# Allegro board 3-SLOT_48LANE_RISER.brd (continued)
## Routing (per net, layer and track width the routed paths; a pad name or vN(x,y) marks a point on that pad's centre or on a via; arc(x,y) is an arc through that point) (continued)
PE_SLV_RX_DN<15>: length 8.6
  TOP w0.135: C102.2 13.17,79.65 13.02,79.65 9.99,79.18 9.4,79.18 v2(9.17,79.41)
  BOTTOM w0.135: J8.24 12.29,79.33 12.14,79.18 9.4,79.18 v2(9.17,79.41)
PE_SLV_RX_DP<0>: length 6
  TOP w0.135: v2(10.82,38.79) 11.03,38.99 13.98,38.99 C23.2
  BOTTOM w0.135: J7.2 12.31,38.87 12.16,39.02 11.06,39.02 v2(10.82,38.79)
PE_SLV_RX_DP<1>: length 9.2
  TOP w0.135: C24.2 13.99,41.01 12.52,41.01 10.32,40.82 v6(10.18,40.82) 9.43,40.82 v2(9.2,40.59)
  BOTTOM w0.135: v2(9.2,40.59) 9.43,40.82 12.17,40.82 12.31,40.68 J7.5
PE_SLV_RX_DP<2>: length 6
  TOP w0.135: C25.2 13.93,43.11 13.35,43.11 v6(12.89,42.95) 11.97,42.63 11.08,42.63 v2(10.85,42.4)
  BOTTOM w0.135: J7.8 12.32,42.48 12.17,42.62 11.07,42.62 v2(10.85,42.4)
PE_SLV_RX_DP<3>: length 9.3
  TOP w0.135: v2(9.22,44.2) 9.45,44.43 11.29,44.43 v6(12.91,44.99) 13.35,45.14 13.93,45.14 C26.2
  BOTTOM w0.135: v2(9.22,44.2) 9.44,44.42 12.17,44.42 12.32,44.27 J7.11
PE_SLV_RX_DP<4>: length 6.1
  TOP w0.135: C79.2 13.93,47.17 13.46,47.17 v6(13.17,47.02) 11.9,46.34 11.9,46.33 11.61,46.18 11.1,46.18 v2(10.9,45.98)
  BOTTOM w0.135: J7.14 12.32,46.08 12.18,46.22 11.14,46.22 v2(10.9,45.98)
PE_SLV_RX_DP<5>: length 9.6
  TOP w0.135: v2(9.2,47.81) 9.42,48.03 v6(10.07,48.03) 11.28,48.03 12.19,48.36 13.25,49.16 13.62,49.23 13.91,49.23 C80.2
  BOTTOM w0.135: J7.17 12.3,47.87 12.16,48.02 9.41,48.02 v2(9.2,47.81)
PE_SLV_RX_DP<6>: length 6.2
  TOP w0.135: C81.2 13.98,51.18 13.36,51.18 13.18,51.1 12.1,50.12 11.9,50 11.56,49.81 11.15,49.81 v2(10.92,49.58)
  BOTTOM w0.135: v2(10.92,49.58) 11.16,49.82 12.18,49.82 12.33,49.68 J7.20
PE_SLV_RX_DP<7>: length 9.8
  TOP w0.135: v2(9.2,51.41) 9.43,51.64 11.22,51.64 12.13,52.02 13.05,52.93 13.55,53.25 13.94,53.25 C82.2
  BOTTOM w0.135: v2(9.2,51.41) 9.41,51.62 12.19,51.62 12.34,51.48 J7.23
PE_SLV_RX_DP<8>: length 5.4
  TOP w0.135: C83.2 13.17,65.12 12.85,65.12 11.78,66.12 11.32,66.27 11.15,66.27 v2(10.92,66.04)
  BOTTOM w0.135: J8.2 12.25,66.13 12.1,66.27 11.15,66.27 v2(10.92,66.04)
PE_SLV_RX_DP<9>: length 8.6
  TOP w0.135: v2(9.22,67.85) 9.45,68.08 10.4,68.08 v6(11.02,67.95) 11.92,67.76 12.71,67.21 12.79,67.15 13.17,67.15 C84.2
  BOTTOM w0.135: J8.5 12.24,67.93 12.1,68.07 9.45,68.07 v2(9.22,67.85)
PE_SLV_RX_DP<10>: length 5.2
  TOP w0.135: v2(10.92,69.65) 11.15,69.88 11.4,69.88 12.9,69.18 13.17,69.18 C85.2
  BOTTOM w0.135: v2(10.92,69.65) 11.15,69.87 12.15,69.87 12.3,69.73 J8.8
PE_SLV_RX_DP<11>: length 8.5
  TOP w0.135: v2(9.2,71.46) 9.43,71.68 10.18,71.68 v6(10.66,71.6) 12.88,71.22 12.9,71.21 13.17,71.21 C86.2
  BOTTOM w0.135: v2(9.2,71.46) 9.41,71.67 12.18,71.67 12.33,71.53 J8.11
PE_SLV_RX_DP<12>: length 5
  TOP w0.135: C87.2 13.17,73.25 12.85,73.25 11.35,73.46 11.15,73.46 v2(10.92,73.23)
  BOTTOM w0.135: J8.14 12.3,73.33 12.16,73.47 11.16,73.47 v2(10.92,73.23)
PE_SLV_RX_DP<13>: length 8.5
  TOP w0.135: v2(9.17,75.06) 9.4,75.29 v6(10.14,75.29) 13.15,75.29 C88.2
  BOTTOM w0.135: v2(9.17,75.06) 9.38,75.27 12.16,75.27 12.31,75.13 J8.17
PE_SLV_RX_DP<14>: length 5
  TOP w0.135: v2(10.92,76.84) 11.15,77.07 11.39,77.07 12.94,77.31 13.17,77.31 C89.2
  BOTTOM w0.135: v2(10.92,76.84) 11.16,77.07 12.16,77.07 12.31,76.93 J8.20
PE_SLV_RX_DP<15>: length 8.6
  TOP w0.135: v2(9.17,78.64) 9.4,78.87 10.02,78.87 13.05,79.34 13.17,79.34 C90.2
  BOTTOM w0.135: v2(9.17,78.64) 9.4,78.87 12.14,78.87 12.29,78.73 J8.23
PE_SLV_TX_DN<0>: length 49
  BOTTOM w0.135: J7.48 16.49,39.48 16.63,39.33 18.14,39.33 20.01,39.92 21.23,40.77 21.27,40.99 21.78,41.35 22,41.31 22.36,41.56 22.4,41.78 22.91,42.13 23.12,42.1 25.06,43.46 25.1,43.65 25.58,43.99 25.77,43.95 26.13,44.21 26.17,44.4 26.65,44.74 26.84,44.7 27.64,45.26 33.05,52.99 v6(35.52,56.51) 37.51,59.36 44.62,64.33 48.97,65.1 52.01,65.64 52.7,66.33 52.7,66.52 U1.AE1
PE_SLV_TX_DN<1>: length 48.3
  BOTTOM w0.089: U1.AE2 52.28,67.39 51.32,67.39 51.25,67.38 51.19,67.42 51.16,67.42
  BOTTOM w0.135: J7.45 16.49,41.27 16.64,41.13 17.86,41.13 19.41,41.61 20.2,42.17 20.24,42.41 20.7,42.73 20.93,42.68 21.29,42.94 21.33,43.16 21.8,43.49 22.03,43.45 27.36,47.18 28.32,48.55 28.28,48.76 28.6,49.22 28.81,49.25 29.06,49.61 29.02,49.82 29.35,50.28 29.55,50.31 31.68,53.36 31.65,53.56 31.97,54.02 32.17,54.06 33.82,56.41 33.78,56.62 34.06,57.02 34.27,57.06 v6(35.42,58.69) 37.04,61.01 44.52,66.25 47.66,66.8 51.16,67.42
PE_SLV_TX_DN<2>: length 48.4
  BOTTOM w0.089: 49.52,68.35 49.55,68.35 49.6,68.29 50.24,68.29 50.55,68.35 51.35,68.89 51.92,68.99 52.28,68.99 U1.AE4
  BOTTOM w0.135: J7.42 16.52,43.08 16.67,42.93 17.97,42.93 19.06,43.12 19.79,43.63 19.83,43.84 20.23,44.12 20.44,44.09 20.8,44.34 20.83,44.54 21.23,44.83 21.44,44.79 26.39,48.25 27.28,49.53 27.25,49.72 27.59,50.2 27.77,50.23 28.02,50.59 27.99,50.78 28.33,51.26 28.51,51.29 30.64,54.32 30.61,54.49 30.88,54.89 31.05,54.92 31.31,55.28 31.28,55.45 31.55,55.84 31.72,55.87 33.93,59.02 33.89,59.24 34.21,59.69 34.42,59.73 36.14,62.17 v6(37.61,63.21) 43.95,67.65 46.72,68.14 47.63,68.3 47.63,68.3 47.93,68.35 49.52,68.35
PE_SLV_TX_DN<3>: length 47.9
  BOTTOM w0.089: U1.AE5 52.28,69.79 52.07,69.79 50.67,69.54 49.29,69.54 49.23,69.6 49.21,69.6
  BOTTOM w0.135: 49.21,69.6 47.01,69.6 43.25,68.94 v6(40.42,66.96) 34.78,63.01 30.57,56.99 30.37,56.96 30.02,56.47 30.06,56.27 29.81,55.91 29.61,55.87 29.26,55.38 29.3,55.18 27.29,52.32 27.08,52.28 26.79,51.86 26.83,51.65 26.58,51.29 26.37,51.25 26.07,50.84 26.11,50.63 25.32,49.5 21.26,46.65 21.06,46.69 20.7,46.44 20.66,46.24 20.3,45.98 20.1,46.02 19.74,45.77 19.71,45.57 18.92,45.02 17.28,44.73 16.71,44.73 16.56,44.87 J7.39
PE_SLV_TX_DN<4>: length 47.8
  BOTTOM w0.089: U1.AE7 52.3,71.41 51.95,71.41 51.52,71.33 51.04,71 50.88,70.89 50.31,70.79 50.05,70.79 49.96,70.89 49.57,70.89 49.47,70.79 49.05,70.79 49,70.85 48.97,70.85
  BOTTOM w0.135: J7.36 16.56,46.68 16.7,46.53 17.65,46.53 18.59,46.69 19.32,47.21 19.36,47.42 19.72,47.67 19.93,47.63 20.29,47.89 20.33,48.1 20.69,48.35 20.9,48.31 24.27,50.67 25.2,52 25.16,52.2 25.41,52.56 25.61,52.59 25.87,52.95 25.83,53.15 26.08,53.51 26.28,53.54 28.15,56.22 28.12,56.41 28.48,56.93 28.67,56.96 28.93,57.32 28.89,57.52 29.25,58.04 29.45,58.07 33.37,63.67 v6(36.92,66.16) 42.51,70.07 46.95,70.85 48.97,70.85
PE_SLV_TX_DN<5>: length 47.2
  BOTTOM w0.089: 49.24,72.05 49.27,72.05 49.32,72 50.09,72 51.18,72.19 52.28,72.19 U1.AE8
  BOTTOM w0.135: 49.24,72.05 46.81,72.05 41.93,71.19 v6(33.34,65.18) 31.61,63.97 29.68,61.21 29.48,61.17 29.21,60.78 29.24,60.58 28.08,58.93 27.88,58.9 27.56,58.43 27.6,58.23 27.35,57.87 27.15,57.84 26.82,57.38 26.86,57.18 25.21,54.83 25.01,54.79 24.73,54.4 24.77,54.2 24.52,53.83 24.32,53.8 24.04,53.4 24.07,53.2 23.42,52.26 20.38,50.14 20.2,50.17 19.78,49.88 19.75,49.7 19.39,49.45 19.21,49.48 18.8,49.19 18.76,49 18,48.47 17.2,48.33 16.79,48.33 16.64,48.48 J7.33
PE_SLV_TX_DN<6>: length 46.9
  BOTTOM w0.089: U1.AE10 52.3,73.81 51.66,73.81 51.3,73.75 50.54,73.23 50.35,73.2 49.05,73.2 49,73.25 48.97,73.25
  BOTTOM w0.135: J7.30 16.54,50.27 16.73,50.09 17.4,50.09 18.5,50.78 18.54,50.98 18.91,51.21 19.11,51.17 19.48,51.41 19.52,51.6 19.89,51.84 20.08,51.79 21.14,52.47 21.78,53.38 21.74,53.59 22.02,53.98 22.23,54.02 22.48,54.38 22.44,54.59 22.72,54.98 22.93,55.02 25.49,58.68 25.45,58.88 25.73,59.27 25.93,59.31 26.18,59.67 26.15,59.87 26.42,60.26 26.62,60.3 v6(27.92,62.14) 28.88,63.53 41.49,72.35 46.62,73.25 48.97,73.25
PE_SLV_TX_DN<7>: length 46.5
  BOTTOM w0.089: 48.97,74.46 49,74.46 49.05,74.4 50.18,74.4 50.37,74.59 52.28,74.59 U1.AE11
  BOTTOM w0.135: 48.97,74.46 46.3,74.46 40.92,73.51 38.62,71.89 38.42,71.93 38.06,71.68 38.03,71.48 37.67,71.23 37.48,71.27 37.12,71.01 37.08,70.82 35.17,69.48 34.97,69.51 34.54,69.21 34.5,69.02 34.14,68.76 33.95,68.8 33.52,68.5 33.48,68.3 30.44,66.17 v6(28.61,64.89) 27.1,63.83 25.3,61.27 25.1,61.23 24.85,60.87 24.89,60.67 24.63,60.31 24.43,60.27 24.18,59.91 24.21,59.71 21.8,56.26 21.6,56.22 21.35,55.86 21.38,55.66 20.2,53.98 17.25,51.91 16.66,51.91 16.5,52.08 J7.27
PE_SLV_TX_DN<8>: length 39.3
  BOTTOM w0.089: U1.AE13 52.31,76.22 49.05,76.22 49,76.27 48.97,76.27
  BOTTOM w0.135: J8.48 16.49,66.73 16.63,66.58 17.82,66.58 17.95,66.71 18.47,66.71 18.61,66.58 19.05,66.58 19.18,66.71 19.7,66.71 19.83,66.58 21.59,66.58 22.6,67.04 22.68,67.24 23.08,67.42 23.28,67.35 23.68,67.53 23.76,67.73 24.16,67.91 24.36,67.84 30.15,70.48 30.23,70.68 30.7,70.9 30.9,70.82 31.3,71 31.37,71.21 31.84,71.42 32.04,71.35 37.04,73.63 v6(38.52,74.3) 39.5,74.75 48.17,76.27 48.97,76.27
PE_SLV_TX_DN<9>: length 39.3
  BOTTOM w0.089: 48.97,77.48 49.03,77.42 49.87,77.42 50.3,76.99 52.28,76.99 U1.AE14
  BOTTOM w0.135: 48.97,77.48 48.06,77.48 47.66,77.4 39.08,75.89 v6(36.4,74.78) 31.34,72.69 31.15,72.77 30.74,72.6 30.66,72.41 30.26,72.24 30.07,72.32 29.66,72.15 29.58,71.96 23.85,69.58 23.65,69.67 23.21,69.48 23.13,69.28 22.72,69.12 22.52,69.2 22.08,69.02 22,68.82 20.94,68.38 19.97,68.38 19.82,68.53 19.28,68.53 19.13,68.38 18.69,68.38 18.54,68.53 18,68.53 17.85,68.38 16.64,68.38 16.49,68.53 J8.45
PE_SLV_TX_DN<10>: length 38.9
  BOTTOM w0.089: 48.97,78.7 49,78.7 49.05,78.64 49.4,78.64 49.49,78.74 49.94,78.74 50.04,78.64 52.33,78.64 U1.AE16
  BOTTOM w0.135: 48.97,78.7 47.95,78.7 v6(44.41,78.07) 42.97,77.82 36.45,76.67 29.77,73.9 29.57,73.98 29.13,73.8 29.05,73.61 23.91,71.48 23.7,71.57 23.26,71.39 23.17,71.17 22.77,71 22.56,71.09 22.11,70.91 22.03,70.7 20.77,70.18 19.71,70.18 19.56,70.33 19.12,70.33 18.97,70.18 18.53,70.18 18.37,70.33 17.93,70.33 17.78,70.18 16.67,70.18 16.52,70.33 J8.42
PE_SLV_TX_DN<11>: length 39
  BOTTOM w0.089: U1.AE17 52.28,79.39 51.26,79.39 51.2,79.45 51.14,79.5 50.75,79.5 50.69,79.45 50.64,79.39 50.33,79.39 49.88,79.84 49.05,79.84 49,79.9 48.97,79.9
  BOTTOM w0.135: J8.39 16.56,72.13 16.71,71.98 17.69,71.98 17.84,72.13 18.28,72.13 18.44,71.98 18.88,71.98 19.03,72.13 19.47,72.13 19.62,71.98 21.12,71.98 22.49,72.54 22.57,72.74 22.98,72.91 23.18,72.83 23.58,73 23.67,73.2 24.07,73.37 24.27,73.28 29.15,75.3 29.23,75.5 29.64,75.67 29.84,75.59 31.06,76.1 34.87,77.67 v6(40.63,78.69) 47.51,79.9 47.84,79.9 47.93,79.98 48.47,79.98 48.55,79.9 48.97,79.9
PE_SLV_TX_DN<12>: length 38.7
  BOTTOM w0.089: 48.97,81.1 49,81.1 49.05,81.05 49.81,81.05 49.94,80.91 50.56,80.91 50.7,81.05 51.09,81.05 51.23,80.91 52.2,80.91 U1.AE19
  BOTTOM w0.135: 48.97,81.1 47.4,81.1 v6(35.78,79.05) 33.17,78.59 29.71,77.16 29.53,77.24 29.05,77.04 28.98,76.86 25.07,75.24 24.87,75.32 24.42,75.13 24.34,74.94 23.93,74.77 23.74,74.85 23.28,74.66 23.2,74.46 21.54,73.78 19.78,73.78 19.7,73.85 19.63,73.93 19.19,73.93 19.11,73.85 19.04,73.78 18.6,73.78 18.53,73.85 18.45,73.93 18.01,73.93 17.94,73.85 17.86,73.78 16.7,73.78 16.56,73.93 J8.36
PE_SLV_TX_DN<13>: length 38.6
  BOTTOM w0.089: U1.AE20 52.28,81.79 51.67,81.79 51.21,82.25 50.65,82.25 50.6,82.3 50.55,82.35 50.15,82.35 50.1,82.3 50.05,82.25 49.03,82.25 48.97,82.3
  BOTTOM w0.135: J8.33 16.64,75.73 16.79,75.58 17.69,75.58 17.76,75.64 17.76,75.65 17.83,75.71 18.27,75.71 18.33,75.65 18.33,75.64 18.4,75.58 18.84,75.58 18.91,75.64 18.91,75.65 18.97,75.71 19.41,75.71 19.48,75.65 19.48,75.64 19.55,75.58 21.67,75.58 23.54,76.35 23.63,76.56 24.03,76.73 24.24,76.64 24.65,76.81 24.74,77.02 25.14,77.19 25.35,77.1 28.16,78.26 28.23,78.44 28.69,78.63 28.87,78.56 29.98,79.02 29.98,79.02 30.96,79.42 36.49,80.4 v6(37.78,80.63) 47.28,82.3 48.97,82.3
PE_SLV_TX_DN<14>: length 38.4
  BOTTOM w0.089: 48.97,83.51 49.03,83.45 52.34,83.45 U1.AE22
  BOTTOM w0.135: J8.30 16.54,77.53 16.73,77.34 17.84,77.34 17.92,77.42 18,77.5 18.44,77.5 18.52,77.42 18.6,77.34 19.04,77.34 19.12,77.42 19.2,77.5 19.64,77.5 19.72,77.42 19.8,77.34 22.29,77.34 23.57,77.87 23.65,78.06 24.05,78.22 24.24,78.15 24.65,78.31 24.73,78.5 25.13,78.67 25.32,78.59 29.76,80.43 31.02,80.66 31.13,80.82 31.64,80.91 31.8,80.79 v6(34.51,81.27) 45.11,83.14 45.2,83.27 45.76,83.37 45.89,83.28 47.17,83.51 47.81,83.51 47.92,83.62 48.41,83.62 48.52,83.51 48.97,83.51
PE_SLV_TX_DN<15>: length 38.4
  BOTTOM w0.089: 48.97,84.71 49,84.71 49.05,84.65 49.7,84.65 50.16,84.19 52.28,84.19 U1.AE23
  BOTTOM w0.135: 48.97,84.71 47.7,84.71 47.54,84.86 47.1,84.86 46.95,84.71 46.05,84.71 v6(32.93,82.39) 31.34,82.11 31.16,82.24 30.72,82.16 30.6,81.98 29.12,81.72 25.59,80.26 25.41,80.33 24.97,80.15 24.89,79.97 24.49,79.8 24.31,79.87 23.86,79.69 23.79,79.51 22.96,79.16 20.79,79.16 20.71,79.24 20.63,79.32 20.19,79.32 20.11,79.24 20.03,79.16 19.59,79.16 19.51,79.24 19.43,79.32 19,79.32 18.92,79.24 18.84,79.16 16.66,79.16 16.5,79.33 J8.27
PE_SLV_TX_DP<0>: length 49
  BOTTOM w0.135: J7.49 16.44,38.87 16.59,39.02 18.19,39.02 20.15,39.64 27.86,45.04 v6(33.3,52.81) 35.77,56.33 36.54,57.44 37.73,59.14 44.74,64.05 48.97,64.79 52.16,65.35 53.01,66.2 53.01,66.52 U1.AD1
PE_SLV_TX_DP<1>: length 48.4
  BOTTOM w0.089: U1.AD2 53.04,67.57 52.67,67.2 51.34,67.2 51.28,67.18 51.24,67.12 51.22,67.12
  BOTTOM w0.135: J7.46 16.47,40.68 16.61,40.82 17.91,40.82 19.54,41.34 23.41,44.05 27.58,46.96 34.24,56.48 35.67,58.51 35.67,58.51 36.71,60.01 v6(36.82,60.16) 37.26,60.79 44.64,65.96 47.66,66.49 51.22,67.12
PE_SLV_TX_DP<2>: length 48.4
  BOTTOM w0.089: U1.AD4 52.73,68.8 51.93,68.8 51.42,68.71 50.63,68.17 50.32,68.1 49.6,68.1 49.55,68.05 49.52,68.05
  BOTTOM w0.135: 49.52,68.05 48.05,68.05 47.68,68 44.07,67.36 v6(38.82,63.68) 37.79,62.96 36.35,61.96 26.6,48.03 19.18,42.83 17.98,42.62 17.96,42.62 16.64,42.62 16.49,42.48 J7.43
PE_SLV_TX_DP<3>: length 48
  BOTTOM w0.089: U1.AD5 52.73,69.6 52.08,69.6 50.69,69.35 49.29,69.35 49.23,69.3 49.21,69.3
  BOTTOM w0.135: J7.40 16.57,44.27 16.72,44.42 17.31,44.42 19.04,44.73 25.54,49.28 35,62.79 40.59,66.71 v6(41.83,67.57) 43.37,68.65 47.03,69.3 49.21,69.3
PE_SLV_TX_DP<4>: length 47.9
  BOTTOM w0.089: 48.97,70.55 49,70.55 49.05,70.6 50.39,70.6 50.95,70.71 51.14,70.84 51.59,71.15 51.97,71.22 52.69,71.22 53.04,71.57 U1.AD7
  BOTTOM w0.135: J7.37 16.55,46.08 16.7,46.22 17.68,46.22 18.7,46.4 24.49,50.45 33.59,63.45 37.1,65.91 v6(38.32,66.77) 42.63,69.78 46.98,70.55 48.97,70.55
PE_SLV_TX_DP<5>: length 47.2
  BOTTOM w0.089: U1.AD8 52.73,72 51.19,72 50.1,71.81 49.32,71.81 49.27,71.75 49.24,71.75
  BOTTOM w0.135: J7.34 16.62,47.87 16.77,48.02 17.23,48.02 18.11,48.18 23.64,52.04 31.83,63.75 33.51,64.93 v6(34.89,65.89) 42.05,70.9 46.84,71.75 49.24,71.75
PE_SLV_TX_DP<6>: length 47
  BOTTOM w0.089: U1.AD10 52.76,73.62 52.13,73.62 52.12,73.62 51.68,73.62 51.37,73.57 50.61,73.05 50.43,73.01 49.05,73.01 49,72.95 48.97,72.95
  BOTTOM w0.135: 48.97,72.95 46.64,72.95 41.61,72.06 v6(30.47,64.27) 29.1,63.31 28.17,61.97 27.81,61.46 27.81,61.45 21.36,52.24 17.49,49.78 16.65,49.78 16.55,49.68 J7.31
PE_SLV_TX_DP<7>: length 46.6
  BOTTOM w0.089: U1.AD11 53.04,74.76 52.67,74.4 50.44,74.4 50.26,74.21 49.05,74.21 49,74.15 48.97,74.15
  BOTTOM w0.135: 48.97,74.15 46.33,74.15 41.04,73.22 v6(30.61,65.92) 28.79,64.64 27.32,63.61 20.42,53.76 17.35,51.61 16.59,51.61 16.45,51.48 J7.28
PE_SLV_TX_DP<8>: length 39.4
  BOTTOM w0.089: U1.AD13 52.6,76.01 52.5,76.02 52.17,76.02 52.16,76.03 49.05,76.03 49,75.97 48.97,75.97
  BOTTOM w0.135: J8.49 16.44,66.13 16.59,66.27 21.66,66.27 v6(37.17,73.35) 38.65,74.02 39.59,74.45 48.19,75.97 48.97,75.97
PE_SLV_TX_DP<9>: length 39.4
  BOTTOM w0.089: 48.97,77.17 49,77.17 49.05,77.23 49.79,77.23 50.22,76.8 52.73,76.8 U1.AD14
  BOTTOM w0.135: 48.97,77.17 48.09,77.17 47.21,77.02 39.16,75.6 36.51,74.5 v6(34.88,73.82) 21,68.07 16.61,68.07 16.47,67.93 J8.46
PE_SLV_TX_DP<10>: length 39
  BOTTOM w0.089: 48.97,78.39 49,78.39 49.05,78.45 52.19,78.45 52.23,78.42 52.55,78.42 53.25,78.75 U1.AD16
  BOTTOM w0.135: J8.43 16.49,69.73 16.64,69.87 20.83,69.87 36.54,76.38 v6(43.03,77.52) 44.46,77.77 47.98,78.39 48.97,78.39
PE_SLV_TX_DP<11>: length 39.1
  BOTTOM w0.089: 48.97,79.6 49,79.6 49.05,79.65 49.8,79.65 50.25,79.2 52.67,79.2 53.04,79.56 U1.AD17
  BOTTOM w0.135: 48.97,79.6 47.54,79.6 v6(42.22,78.66) 40.68,78.39 34.96,77.38 21.18,71.67 16.72,71.67 16.57,71.53 J8.40
PE_SLV_TX_DP<12>: length 38.8
  BOTTOM w0.089: 48.97,80.8 49,80.8 49.05,80.85 49.73,80.85 49.86,80.72 52.62,80.72 U1.AD19
  BOTTOM w0.135: 48.97,80.8 47.43,80.8 v6(37.88,79.11) 35.84,78.75 33.25,78.3 21.6,73.47 16.7,73.47 16.55,73.33 J8.37
PE_SLV_TX_DP<13>: length 38.7
  BOTTOM w0.089: 48.97,82 48.99,82 49.04,82.06 51.13,82.06 51.59,81.6 52.53,81.6 U1.AD20
  BOTTOM w0.135: J8.34 16.62,75.13 16.77,75.27 21.73,75.27 31.04,79.13 36.54,80.1 37.83,80.33 v6(39.61,80.64) 47.3,82 48.97,82
PE_SLV_TX_DP<14>: length 38.5
  BOTTOM w0.089: 48.97,83.2 49,83.2 49.05,83.26 52.19,83.26 52.23,83.22 52.69,83.22 53.04,83.56 U1.AD22
  BOTTOM w0.135: J8.31 16.55,76.93 16.65,77.03 22.35,77.03 29.85,80.14 v6(32.67,80.64) 34.56,80.97 47.2,83.2 48.97,83.2
PE_SLV_TX_DP<15>: length 38.5
  BOTTOM w0.089: 48.97,84.4 49,84.4 49.05,84.46 49.62,84.46 50.08,84 52.67,84 53.04,84.37 U1.AD23
  BOTTOM w0.135: 48.97,84.4 46.08,84.4 v6(29.87,81.54) 29.21,81.43 23.02,78.86 16.59,78.86 16.45,78.73 J8.28
PE_WAKE_N: length 110.3
  TOP w0.114: v2(286.08,44.15) 285.83,43.89 R8.1 ; R7.1 v2(285.83,84.73) ; R370.1 v2(282.91,23.6)
  IN2 w0.147: v2(282.86,11.79) 282.86,11.84 283.34,12.32 285.04,12.32 286.56,13.84 288.37,13.84 288.8,14.27 288.8,17.86 288.01,18.64 288.01,19.94 287.45,20.5 286.01,20.5 v2(282.91,23.6) 282.91,28.17 285.23,30.49 290.08,30.49 291.72,32.13 291.72,33.86 290.91,34.67 290.91,38.1 289.69,39.32 289.69,41.1 287.57,43.22 287.01,43.22 v2(286.08,44.15) 285.24,44.98 285.24,46.69 288.72,50.16 288.72,62.15 286.79,64.08 286.79,70.38 287.73,71.32 289.16,71.32 289.74,71.91 289.74,74.32 290.68,75.26 290.68,79.07 289.71,80.04 289.71,81.84 288.72,82.83 287.73,82.83 v2(285.83,84.73)
  BOTTOM w0.114: v2(282.86,11.79) 282.86,11.73 284.68,9.91 285.19,9.91 286.56,8.54 286.56,6.58 285.83,5.84 J5.B11
PEX8747_SPARE0: length 3.9
  TOP w0.114: v3(67.99,65.72) 68.77,65.72 68.83,65.66 v4(69.42,65.66) R93.2
  BOTTOM w0.114: U1.F1 67.65,66.36 67.99,66.03 v3(67.99,65.72)
PEX8747_SPARE1: length 3.8
  TOP w0.102: v5(55.32,65.46) 54.81,64.96 R74.2
  BOTTOM w0.114: v5(55.32,65.46) 56.06,66.21 56.06,67.17 56.45,67.56 U1.Y2
PEX8747_SPARE2: length 8.2
  TOP w0.102: v3(58.45,70.36) 58.44,70.36 58.07,69.99 58.07,68.48 57.43,67.84 57.43,65.96 v4(57.02,65.56) 56.85,65.38 R73.1 R72.2
  BOTTOM w0.114: U1.U6 v3(58.45,70.36)
PEX8747_SPARE3: length 3.8
  TOP w0.114: R75.1 v5(64.45,65.32)
  BOTTOM w0.114: v5(64.45,65.32) 64.02,65.75 64.02,66.47 64.06,66.51 64.06,67.27 64.35,67.57 U1.K2
PEX_EEP_CS_N: length 8.3
  TOP w0.114: v3(64.85,81.57) 65.25,81.97 65.25,83.59 65.74,84.07 v1(65.74,87) 65.74,88.25 R118.1
  BOTTOM w0.114: U1.K19 64.47,81.16 64.85,81.55 v3(64.85,81.57)
PEX_EEP_CS_R_N: length 5.2
  TOP w0.114: R128.2 R118.2 65.23,90.5 v1(64.82,90.9) 64.34,91.38 U6.1
PEX_EEP_HOLD_N: length 2.1
  TOP w0.114: U6.7 65.61,100.44 R129.2
PEX_EEP_SCLK: length 5.5
  TOP w0.114: R130.2 v1(68.4,87.5) 68.05,87.15 v5(68.05,84.91)
  BOTTOM w0.114: U1.F22 67.68,83.56 68.05,83.94 v5(68.05,84.91)
PEX_EEP_SCLK_R: length 10.3
  TOP w0.114: U6.6 66.88,96.77 69.04,94.61 69.04,91.69 v1(68.53,91.19) 68.4,91.06 R130.1
PEX_EEP_SI: length 8.3
  TOP w0.114: v3(68.05,81.57) 68.45,81.97 68.45,85.04 v1(69.42,86) R131.2
  BOTTOM w0.114: U1.F19 v3(68.05,81.57)
PEX_EEP_SI_R: length 9.9
  TOP w0.114: R131.1 69.67,89.81 69.67,90.81 v1(69.8,90.93) 69.8,91.19 69.67,91.31 69.67,94.74 68.15,96.27 U6.5
PEX_EEP_SO: length 10.4
  TOP w0.114: v3(60.85,79.97) 60.85,80.22 60.46,80.62 60.46,81.76 60.66,81.97 61.01,81.97 61.24,82.2 61.24,86.82 v1(61.8,87.38) 62.18,87.76 R119.1
  BOTTOM w0.114: U1.R18 v3(60.85,79.97)
PEX_EEP_SO_R: length 10.1
  TOP w0.114: U6.2 65.61,94.36 65.1,94.87 63.7,94.87 63.32,94.49 63.32,91.65 v1(62.58,90.91) 62.18,90.51 R119.2 R121.2
PEX_GPIO1: length 6.3
  TOP w0.102: v3(61.65,67.96) 61.06,67.96 v4(60.78,67.69)
  TOP w0.114: v4(60.78,67.69) 60.48,67.39 60.48,64.97 R47.2 R44.1
  BOTTOM w0.114: U1.N3 62.05,68.36 v3(61.65,67.96)
PEX_GPIO2: length 27.1
  TOP w0.102: v3(56.05,69.56) 56.05,69.73 55.66,70.12 55.66,85.22
  TOP w0.114: R45.1 R48.2 v2(57.99,93.09) 57.99,87.73 55.66,85.4 55.66,85.22
  BOTTOM w0.114: U1.Y5 v3(56.05,69.56)
PEX_GPIO3: length 43.8
  TOP w0.114: v2(32.97,104.65) 33.22,104.9 R49.2
  IN1 w0.102: v3(57.65,75.16) 57.24,75.58 56.63,75.58 56.26,75.95 52.68,75.95 52.38,76.25 51.98,76.25 50.77,77.47 50.73,77.47
  IN1 w0.147: v2(32.97,104.65) 32.97,104.39 33.28,104.09 33.28,99.12 36.1,96.29 36.1,92.1 50.73,77.47
  BOTTOM w0.114: U1.V11 v3(57.65,75.16)
PEX_GPIO6: length 54.3
  TOP w0.114: R52.2 25.86,104.52 v2(25.99,104.39)
  IN1 w0.102: 47.66,73.73 49.33,72.06 51.19,72.06 53.26,69.98 55.74,69.98 56.05,70.3 v3(56.05,70.36)
  IN1 w0.147: 47.66,73.73 46.31,75.08 46.31,76.45 39.31,83.45 34.4,83.45 32.78,85.07 32.78,90.29 31.71,91.37 31.71,95.49 27.46,99.74 27.46,102.92 v2(25.99,104.39)
  BOTTOM w0.114: U1.Y6 v3(56.05,70.36)
PEX_GPIO7: length 7.2
  TOP w0.102: v3(63.25,70.36) 63.09,70.36 62.87,70.14 62.87,68.44 v4(62.44,68.01) 62.44,67.15 62.56,67.02 62.56,64.92 R53.2
  BOTTOM w0.114: U1.M6 v3(63.25,70.36)
PEX_GPIO10: length 55.1
  TOP w0.114: v2(24.72,104.14) 24.84,104.27 R56.2
  IN1 w0.102: v3(56.05,68.76) 55.84,68.76 55.44,68.36 54.17,68.36 53.7,68.83 52.71,68.83 50.47,71.07 49.18,71.07 49.16,71.09 48.97,71.09
  IN1 w0.147: 48.97,71.09 48.76,71.09 37,82.85 34.15,82.85 32.18,84.82 32.18,90.04 31.11,91.12 31.11,95.24 25.34,101.01 25.34,103.52 v2(24.72,104.14)
  BOTTOM w0.114: U1.Y4 v3(56.05,68.76)
PEX_PERST_BUF_N: length 8.2
  TOP w0.114: Q2.D 167.61,113.9 R351.2 v1(164.92,113.9) 163.35,113.9 C193.1 162.85,114.4 C192.1 161.34,114.43 U13.2
PEX_PERST_N: length 139.2
  TOP w0.102: 58.85,87.38 58.85,87.22 56.44,84.81 56.44,70.94 56.6,70.78 57.37,70.78 57.65,71.06 v3(57.65,71.16)
  TOP w0.114: 58.85,87.38 58.85,89.28 v1(58.96,89.38) 59.79,90.22 59.79,98.22 64.62,103.05 105.08,103.05 107.04,101.09 110.54,101.09 117.91,108.46 153.85,108.46 156.77,111.38 156.77,114.53 157.32,115.08 U13.4
  BOTTOM w0.102: U1.V7 58.05,71.56 v3(57.65,71.16)
PEX_RORT_GOOD0_N: length 4.6
  TOP w0.102: R46.2 70.44,65.28 v4(71.05,65.89) 70.45,66.48 v3(70.45,67.16)
  BOTTOM w0.114: v3(70.45,67.16) 70.45,67.97 U1.B3
PEX_RORT_GOOD4_N: length 3.5
  TOP w0.102: R50.2 58.88,65.33 58.93,65.38 v4(58.93,65.84)
  TOP w0.114: v4(58.93,65.84) 59.25,66.16 v3(59.25,67.16)
  BOTTOM w0.114: U1.T2 v3(59.25,67.16)
PEX_RORT_GOOD5_N: length 58.5
  TOP w0.114: v2(28.27,102.62) 30.05,102.62 30.81,103.38 30.81,106.91 R51.2
  IN1 w0.102: v3(56.85,70.36) 56.46,70.76 56.46,71.31 56.22,71.55 53.86,71.55 53.29,72.11 52.1,72.11 51.36,72.85 49.76,72.85 47.66,74.95
  IN1 w0.147: 47.66,74.95 46.94,75.67 46.94,77.44 40.33,84.05 34.65,84.05 33.38,85.32 33.38,90.54 32.31,91.62 32.31,95.74 28.06,99.99 28.06,102.4 v2(28.27,102.62)
  BOTTOM w0.114: U1.W6 v3(56.85,70.36)
PEX_RORT_GOOD8_N: length 4.7
  TOP w0.102: v3(59.25,67.96) v4(58.41,67.12)
  TOP w0.114: R54.2 57.86,66.57 v4(58.41,67.12)
  BOTTOM w0.114: v3(59.25,67.96) 59.65,68.36 U1.T3
PEX_RORT_GOOD9_N: length 58.2
  TOP w0.114: v2(26.49,103) 25.35,104.14 25.35,107.84 R55.2
  IN1 w0.102: 48.97,71.39 49.16,71.39 49.27,71.28 50.56,71.28 52.66,69.18 56.28,69.18 56.66,69.56 v3(56.85,69.56)
  IN1 w0.147: 48.97,71.39 48.89,71.39 37.12,83.15 34.28,83.15 32.48,84.95 32.48,90.17 31.41,91.25 31.41,95.37 26.49,100.28 v2(26.49,103)
  BOTTOM w0.114: U1.W5 57.25,69.96 v3(56.85,69.56)
PG_CKPWRGD_N: length 4
  TOP w0.114: R3.2 Q3.D Q4.G
PG_MOS: length 3
  TOP w0.114: Q3.G 297.32,50.79 R298.2 R297.2
PST_PE_SLOT1_N: length 20.6
  TOP w0.114: v2(280.75,28.07) 280.13,28.69 U11.4 280.11,29.06 R317.2
  IN2 w0.147: J1.A11 285.83,15.82 286.64,16.64 286.64,18.11 284.99,19.76 284.25,19.76 283.64,20.37 281.59,20.37 280.63,21.33 280.63,22.85 281.36,23.58 281.36,25.37 280.82,25.91 280.82,27.99 v2(280.75,28.07)
PST_PE_SLOT2_N: length 8.1
  TOP w0.114: J2.A11 285.83,34.99 282.3,31.46 282.3,30.45 282.55,30.21 R353.2 282.91,29.59 282.92,29.58 U17.4
PST_PE_SLOT3_N: length 8.1
  TOP w0.114: U16.4 282.92,70.36 282.91,70.37 R352.2 282.55,70.85 282.4,70.99 282.4,72.14 285.83,75.57 J3.A11
PU_EEP_WP_R_N: length 4
  TOP w0.114: U6.3 v1(66.88,91.19) 67.39,90.68 R120.2
PU_EMC1412_ALERT: length 3.5
  BOTTOM w0.114: U4.6 310.87,79.07 v4(311.71,79.91) 311.94,80.14 R341.2
PU_EMC1412_TEM: length 2.9
  BOTTOM w0.114: U4.4 306.3,80.22 v4(306.3,81.15) R302.2
PU_PCA9548_SC0: length 5.8
  TOP w0.114: R96.2 306.53,45.24 305.87,44.58 305.87,42.52 v2(305.56,42.21) 305.44,42.09 U2.5
PU_PCA9548_SC2: length 5.7
  TOP w0.114: R100.2 301.96,41.86 v2(302.38,41.44) 302.84,40.98 U2.9
PU_PCA9548_SD0: length 6
  TOP w0.114: U2.4 306.09,41.7 306.61,42.21 v2(306.61,43.97) 306.61,44.38 R95.2
PU_PCA9548_SD2: length 5.9
  TOP w0.114: U2.8 303.49,41.16 302.62,42.04 v2(302.62,43.13) 302.62,44.96 R99.2
PU_VOE4_N: length 1.9
  TOP w0.114: R6.2 296.6,60.1 U9.32 298.34,60.1
PU_VOE5_N: length 1.9
  TOP w0.114: 298.34,57.7 U9.38 296.81,57.7 R137.2
RST_PE_SLOT_N: length 243.6
  TOP w0.114: Q1.G 170.86,109.79 171.27,110.21 171.27,114.17 173.86,116.76 196.09,116.76 211.18,101.68 v2(263.36,101.68) ; U17.2 282.27,26.01 v2(282.02,25.76) 279.81,25.76 279.48,26.09 U11.2 ; v2(281.21,21.69) 281.87,21.03 281.87,18.87 282.65,18.08 282.65,17.14 282.45,16.94 282.45,15.54 282.63,15.37 282.63,14.2 282.02,13.59 282.02,11.51 283.64,9.88 284.51,9.88 285.56,9.45 286.72,8.29 286.72,6.6 285.83,5.71 J5.A11 ; U16.2 282.27,66.7 v2(282.17,66.6)
  IN2 w0.147: v2(281.21,21.69) 282.08,22.57 282.08,25.64 282.02,25.7 v2(282.02,25.76) 281.97,25.81 281.97,27.36 281.41,27.91 281.41,28.32 284.2,31.11 289.51,31.11 289.87,31.47 289.87,33.83 288.93,34.77 288.93,37.87 287.83,38.96 287.83,41.71 286.79,42.75 285.52,42.75 284.63,43.64 284.63,47.07 288.11,50.55 288.11,60.27 282.17,66.22 v2(282.17,66.6) 282.17,68.48 286.72,73.03 287.25,73.03 287.94,73.71 287.94,74.47 288.75,75.29 288.75,78.94 287.83,79.86 287.83,81.56 284.91,84.48 284.91,86.11 281.18,89.84 276.13,89.84 264.29,101.68 v2(263.36,101.68)
RST_PEX_MOS_N: length 5.6
  TOP w0.114: R348.2 166.96,110.72 166.98,110.74 Q1.D 167.89,112.25 v2(168.86,113.22) Q2.G
SLOT2_JTAG_TCK: length 4.5
  TOP w0.114: J2.A5 291.83,31.61 R275.2
SLOT2_JTAG_TDI: length 2.5
  TOP w0.114: R262.2 290.83,31.59 J2.A6
SLOT2_JTAG_TDO: length 4.5
  TOP w0.114: R263.2 289.83,31.58 J2.A7
SLOT2_JTAG_TMS: length 2.5
  TOP w0.114: R264.2 289.08,31.32 289.08,33.01 J2.A8
SLOT2_JTAG_TRST_N: length 4.9
  TOP w0.114: J2.B9 287.83,42.62 R261.2
SLOT3_JTAG_TCK: length 4.6
  TOP w0.114: J3.A5 291.83,73.12 292.56,72.39 R260.2
SLOT3_JTAG_TDI: length 2.5
  TOP w0.114: J3.A6 290.83,73.36 291.54,72.64 R257.2
SLOT3_JTAG_TDO: length 4.5
  TOP w0.114: R258.2 290.53,72.57 289.83,73.27 J3.A7
SLOT3_JTAG_TMS: length 2.5
  TOP w0.114: J3.A8 288.83,73.2 289.51,72.52 R259.2
SLOT3_JTAG_TRST_N: length 4.8
  TOP w0.114: J3.B9 287.86,78.43 R252.2
STRAP_I2C_SMBUS_CFG_EN_N: length 59
  TOP w0.114: R113.2 24.33,107.04 24.33,105.9 R114.1 23.83,102.87 v2(24.46,102.23)
  IN1 w0.102: 48.97,70.49 49.15,70.49 49.27,70.61 50.29,70.61 53.35,67.55 55.48,67.55 55.9,67.96 v3(56.05,67.96)
  IN1 w0.147: v2(24.46,102.23) 24.46,101.04 30.51,95 30.51,90.87 31.58,89.8 31.58,84.58 33.9,82.26 36.75,82.26 48.52,70.49 48.97,70.49
  BOTTOM w0.114: U1.Y3 v3(56.05,67.96)
STRAP_I2C_SMBUS_EN: length 7
  TOP w0.102: v3(68.05,68.76) 67.8,68.76 67.41,68.38 ; R111.2 R112.1 67.39,65.48 v4(67.26,65.61)
  TOP w0.109: v4(67.26,65.61) 66.82,66.05 66.82,68.1 67.1,68.38 67.41,68.38
  BOTTOM w0.114: U1.F4 v3(68.05,68.76)
STRAP_PLL_BYPASS_N: length 17
  TOP w0.114: v2(55.83,89.03) 56.47,89.66 56.47,94.25 R117.2
  IN1 w0.102: 57.65,80.53 57.02,81.16 56.61,81.16 56.44,81.33 56.44,86.49 56.59,86.64 56.59,88.27 v2(55.83,89.03)
  IN1 w0.112: 57.65,80.53 v3(57.65,79.97)
  BOTTOM w0.114: U1.V17 58.05,79.57 v3(57.65,79.97)
STRAP_RESERVED0: length 13.9
  TOP w0.114: R70.2 56.97,88.65 v2(55.96,87.63)
  IN1 w0.102: 56.4,80.77 55.63,81.53 55.63,83.01 55.64,83.01 55.64,87.31 v2(55.96,87.63)
  IN1 w0.112: 56.4,80.77 v3(56.85,80.77)
  BOTTOM w0.114: U1.V18 58.05,80.37 57.66,80.77 v3(56.85,80.77)
STRAP_RESERVED5: length 45.4
  TOP w0.114: R59.1 v2(27.89,104.52)
  IN1 w0.102: 47.66,77.57 48.03,77.2 48.03,75.74 50.12,73.66 52.76,73.66 v3(53.65,72.76)
  IN1 w0.147: 47.66,77.57 32.9,92.33 32.9,95.99 29.08,99.82 29.08,103.34 v2(27.89,104.52)
  BOTTOM w0.114: U1.AD9 v3(53.65,72.76)
STRAP_RESERVED7: length 2.3
  TOP w0.114: R61.1 64.7,68.61 v3(64.85,68.76)
  BOTTOM w0.114: v3(64.85,68.76) 64.46,68.37 U1.K3
STRAP_RESERVED9: length 4.7
  TOP w0.102: R65.1 71.09,82.96 v4(70.64,82.96) 70.64,82.09 70.84,81.9 70.84,81.15 v3(70.45,80.77)
  BOTTOM w0.114: U1.B18 v3(70.45,80.77)
STRAP_RESERVED14: length 43.7
  TOP w0.114: v2(32.34,103.5) 32.34,104.78 32.71,105.15 32.71,107.83 R69.2
  IN1 w0.102: 47.66,79.69 50.4,76.95 50.4,76.21 v2(51.06,75.55)
  IN1 w0.147: 47.66,79.69 35.26,92.09 35.26,95.98 32.09,99.15 32.09,103.26 v2(32.34,103.5)
  BOTTOM w0.114: U1.AD12 52.82,75.13 51.48,75.13 v2(51.06,75.55)
STRAP_RESERVED15: length 44.2
  TOP w0.114: v2(35.51,103.63) 35.51,106.28 R64.2
  IN1 w0.102: v3(56.85,76.77) 56.85,76.66 56.34,76.16 52.88,76.16 52.58,76.45 52.17,76.45 48.97,79.65
  IN1 w0.147: 48.97,79.65 36.73,91.9 36.73,102.41 v2(35.51,103.63)
  BOTTOM w0.114: U1.W14 v3(56.85,76.77)
STRAP_RESERVED16: length 18
  TOP w0.114: R67.1 55.96,90.17 55.2,89.41 55.2,88.39 54.56,87.76 v2(54.56,87.63)
  IN1 w0.102: v2(54.56,87.63) 54.56,87.5 54.83,87.23 54.83,80.63 55.08,80.38 56.27,80.38 56.29,80.37 57.05,80.37 57.25,80.16 57.25,77.9 57.59,77.57 v3(57.65,77.57)
  BOTTOM w0.114: v3(57.65,77.57) 58.05,77.17 U1.V14
STRAP_RESERVED19: length 7
  TOP w0.102: v3(71.25,75.16) 71.74,74.68 74.03,74.68 74.45,75.1
  TOP w0.114: 74.45,75.1 74.77,75.41 75.97,75.41 76.39,75 R60.2
  BOTTOM w0.114: U1.B12 v3(71.25,75.16)
STRAP_RESERVED20: length 53.3
  TOP w0.114: R318.1 26.37,107.04 26.37,106.68 26.75,106.3 v2(26.75,105.54)
  IN1 w0.102: v3(53.65,70.36) 53.23,70.36 51.22,72.38 49.65,72.38 47.66,74.36
  IN1 w0.147: v2(26.75,105.54) 26.75,104.27 27.76,103.26 27.76,99.86 32.01,95.62 32.01,91.49 33.08,90.42 33.08,85.2 34.53,83.75 39.48,83.75 46.64,76.59 46.64,75.38 47.66,74.36
  BOTTOM w0.114: U1.AD6 v3(53.65,70.36)
STRAP_RESERVED21: length 53.8
  TOP w0.114: R71.1 v2(22.81,104.52)
  IN1 w0.102: 48.97,70.79 49.16,70.79 49.19,70.82 50.37,70.82 52.68,68.5 53.21,68.5 53.65,68.06 v3(53.65,67.96)
  IN1 w0.147: 48.97,70.79 48.64,70.79 36.88,82.56 34.03,82.56 31.88,84.7 31.88,89.92 30.81,91 30.81,95.12 25.04,100.89 25.04,102.33 22.85,104.52 v2(22.81,104.52)
  BOTTOM w0.381: U1.AD3 53.25,68.36 v3(53.65,67.96)
STRAP_STN1_PORTCFG0: length 13.4
  TOP w0.102: 74.45,74.42 71.45,74.42 70.87,75 70.87,75.32 70.63,75.56 v4(68.91,75.56) 68.91,75.48 68.21,74.78 67.9,74.78 67.64,74.53 67.64,74.17 67.42,73.95 66.78,73.95 66.45,73.62 v3(66.45,73.56)
  TOP w0.114: 74.45,74.42 74.83,74.42 v4(75.06,74.65) 75.41,74.3 R63.1 R62.2
  BOTTOM w0.114: U1.H10 v3(66.45,73.56)
STRAP_STN2_PORTCFG0: length 2.2
  TOP w0.102: R58.1 R57.2 61.67,81.55 v3(61.65,81.57)
  BOTTOM w0.114: U1.N19 62.05,81.17 v3(61.65,81.57)
STRAP_TESTMODE0: length 22.3
  TOP w0.114: R115.2 R116.1 52.27,91.33 v2(52.27,87.76)
  IN1 w0.102: 52.27,85.22 52.27,84.96 52.53,84.71 52.53,78.94 54.31,77.17 57.3,77.17 57.65,76.82 v3(57.65,76.77)
  IN1 w0.147: v2(52.27,87.76) 52.27,85.22
  BOTTOM w0.114: U1.V13 v3(57.65,76.77)
STRAP_UP_PORTSEL0: length 3.3
  TOP w0.102: v3(66.45,80.77) 66.45,80.79 66.86,81.19 66.86,82.67 R68.1
  BOTTOM w0.114: U1.H18 v3(66.45,80.77)
STRAP_UP_PORTSEL1: length 4.4
  TOP w0.102: R66.1 63.64,83.86 63.64,80.95 63.45,80.77 v3(63.25,80.77)
  BOTTOM w0.114: U1.M18 v3(63.25,80.77)
THER_SEN1_DN_1: length 150.8
  TOP w0.254: U10.3 178.19,78.5 178.13,78.56 177.61,78.56 176.63,79.55 176.63,80.98 177.79,82.13 196.11,82.13 210.17,96.2 309.23,96.2 v1(309.55,96.52) 309.87,96.2 312.45,96.2 312.65,96.41 C468.2 316.25,96.41 Q5.2
THER_SEN1_DN_2: length 181.1
  TOP w0.254: U10.5 178.19,77.5 178.13,77.56 157.9,77.56 132.49,102.97 117.78,102.97 v2(117.5,102.69) ; v2(25.27,81.99) 24.99,82.28 C469.2 24.06,82.11 Q6.2
  IN2 w0.254: v2(25.27,81.99) 25.72,82.44 26.76,82.44 27.51,83.19 27.51,88.77 30.94,92.2 41.08,92.2 46.29,97.41 67.35,97.41 72.92,102.97 117.22,102.97 v2(117.5,102.69)
THER_SEN1_DP_1: length 150
  TOP w0.254: U10.2 178.19,79 178.13,78.94 177.77,78.94 177.01,79.7 177.01,80.82 177.94,81.75 196.26,81.75 210.33,95.82 307.74,95.82 v1(308,95.55) 308.27,95.82 312.45,95.82 312.65,95.61 C468.1 314.18,95.61 Q5.3 315.04,95.5 315.99,94.55 Q5.1
THER_SEN1_DP_2: length 181.4
  TOP w0.254: v2(25.27,83.26) 25.09,83.08 C469.1 24.21,83.06 Q6.3 22.58,83.06 21.63,84.01 Q6.1 ; U10.4 178.19,78 178.13,77.94 158.06,77.94 132.65,103.35 117.78,103.35 v2(117.5,103.64)
  IN2 w0.254: v2(25.27,83.26) 25.72,82.82 26.6,82.82 27.13,83.34 27.13,88.93 30.78,92.58 40.92,92.58 46.13,97.79 67.19,97.79 72.76,103.35 117.22,103.35 v2(117.5,103.64)
THER_SEN2_DN: length 345.3
  IN2 w0.254: v2(285.5,90.45) 285.22,90.17 284.2,90.17 282.68,91.69 276.81,91.69 263.3,105.21 187.52,105.21 185.16,102.84 170.44,102.84 168,105.28 72.67,105.28 66.7,99.31 45.34,99.31 40.26,94.23 25.04,94.23 19.84,89.03 19.84,63.41 v7(19.54,63.12)
  BOTTOM w0.254: v2(285.5,90.45) 285.83,90.12 296.04,90.12 299.54,86.61 299.54,81.1 301.72,78.93 304.57,78.93 304.7,79.07 U4.3 ; Q27.2 14.39,58.57 C260.2 17.35,58.44 17.5,58.29 18.59,58.29 19.82,59.53 19.82,62.84 v7(19.54,63.12)
THER_SEN2_DP: length 345.5
  IN2 w0.254: v7(285.5,89.51) 285.22,89.79 284.04,89.79 282.52,91.31 276.65,91.31 263.14,104.83 187.68,104.83 185.32,102.46 170.28,102.46 167.84,104.9 72.83,104.9 66.86,98.93 45.49,98.93 40.41,93.85 25.2,93.85 20.22,88.87 20.22,63.39 v2(20.48,63.12)
  BOTTOM w0.254: Q27.1 15.16,56.94 Q27.3 17.23,57.89 C260.1 17.5,57.91 18.75,57.91 20.2,59.37 20.2,62.84 v2(20.48,63.12) ; U4.2 304.7,78.41 304.57,78.55 301.56,78.55 299.16,80.94 299.16,86.46 295.88,89.74 285.73,89.74 v7(285.5,89.51)
TLA2024_P0V9: length 3.5
  TOP w0.305: U3.4 261.45,29.72 261.18,29.45
  TOP w0.381: R148.2 C190.1 260.63,28.91 261.18,29.45
TLA2024_P1V8: length 3.6
  TOP w0.305: 261.29,28.75 261.62,29.08 U3.5
  TOP w0.381: R146.2 C189.1 260.43,27.89 261.29,28.75
TLA2024_P3V3: length 3.9
  TOP w0.254: U3.6 261.95,28.45 261.44,27.94 v1(261.44,27.08) C180.1 R147.2
TP_A19: length 20.9
  TOP w0.114: J5.A19 275.83,6.57 275.54,6.86 275.54,11.53 275.85,11.84 275.85,13.56 274.93,14.48 274.93,17.55 273.86,18.62 273.86,22.49 v2(273.26,23.1)
TP_A32: length 20.7
  TOP w0.114: v2(260.68,22.61) 260.04,21.96 260.04,18.45 261.01,17.48 261.01,14.27 262.04,13.25 262.04,11.94 263.05,10.93 263.05,6.11 262.83,5.89 J5.A32
TP_A33: length 21.7
  TOP w0.114: v2(258.78,22.61) 259.76,21.62 259.76,18.94 258.8,17.98 258.8,16.69 259.28,16.21 260.25,16.21 260.73,15.72 260.73,14.16 261.76,13.13 261.76,11.58 261.83,11.52 J5.A33
TP_A50: length 22
  TOP w0.114: v2(241.89,22.86) 241.89,18.8 242.77,17.91 242.77,16.89 243.49,16.18 244.43,16.18 244.83,15.77 244.83,14.4 243.79,13.36 243.79,12.32 244.43,11.68 244.43,6.35 244.83,5.95 J5.A50
TP_B12: length 20.9
  BOTTOM w0.114: J5.B12 282.83,5.92 282.59,6.16 282.59,7.68 282.27,8 282.27,9.02 282.91,9.65 282.91,10.54 282.02,11.43 282.02,13.59 282.65,14.22 282.65,15.34 282.42,15.57 282.42,16.79 282.7,17.07 282.7,18.08 281.85,18.94 281.85,21.79 v4(281.15,22.48)
TP_B82: length 15.6
  BOTTOM w0.114: v4(206.96,15.88) 208.33,15.88 212.83,11.38 J5.B82
UNNAMED_60_RES_I68_A: length 1.2
  TOP w0.254: R135.1 263.72,30.83 U3.1
VR_P0V9_BT: length 3.8
  TOP w0.305: PU23.14 v2(67.3,39.74)
  BOTTOM w0.508: PC587.1 66.37,42.16 66.37,40.87 v4(66.45,40.79) 67.3,39.94 v2(67.3,39.74)
VR_P0V9_PVIN: length 21.3
  IN1 w0.305: v3(66.66,46.59) 66.66,46.27 65.42,45.02 64.3,45.02 63.64,44.36 63.64,42.64 65.79,40.48 65.79,37.32 65.22,36.75 59.34,36.75 v2(58.75,37.34)
  BOTTOM w0.305: v3(66.66,46.59) 66.66,46.85 66.03,47.48 PR426.1
  vias: v2(57.9,37.28) v2(61.96,37.56) v2(62.6,37.56) v2(63.23,37.56) v2(63.42,40.64) v2(64.42,39.75) v2(65.05,39.73) v4(60.28,36.96)
VR_P0V9_SW: length 2.2
  BOTTOM w0.381: v2(65.24,43.3) 65.21,43.32 65.21,43.95 v4(65.36,44.09) 66.22,44.09 PC587.2
VR_P1V8_BT: length 3.4
  TOP w0.254: v2(45.46,108.62) 45.32,108.47 PU19.14
  BOTTOM w0.305: PC546.1 46.31,108.2 v4(46.26,108.2) 45.88,108.2 v2(45.46,108.62)
VR_P1V8_PVIN: length 11.3
  IN2 w0.305: v2(43.8,103.49) 43.79,103.5 43.79,104.18 44.3,104.68 46.18,104.68 46.81,105.32 46.81,107.19 47.45,107.82 48.59,107.82 49.35,108.58 v2(49.35,109.73)
  BOTTOM w0.381: PR370.1 43.8,102.88 v2(43.8,103.49)
  vias: v1(48.92,112.06) v2(47.29,108.67) v2(48.06,108.67)
VR_P1V8_SW: length 1.8
  BOTTOM w0.305: v2(48.87,106.43) 48.74,106.43 47.92,105.6 PC546.2
VR_P3V3_BT: length 3.6
  TOP w0.508: v2(296.5,108.66) 295.96,108.66 v1(295.58,108.29) 295.36,108.06 PC514.1
  BOTTOM w0.254: PU17.14 296.41,108.58 v2(296.5,108.66)
VR_P3V3_PVIN: length 21.5
  TOP w0.381: v2(298.33,99.31) PR341.1
  IN1 w0.305: v2(290.4,112.01) 290.91,111.51 293.76,111.51 294.98,110.29 294.98,107.98 293.07,106.07 293.07,104.43 295.08,102.41 295.08,101.14 296.4,99.82 297.82,99.82 v2(298.33,99.31)
  vias: v2(292.56,108.08) v2(293.19,108.08)
VR_P3V3_SW: length 3.2
  TOP w0.508: v2(294.49,105.41) 294.49,104.55 295,104.04 v1(295.11,104.04) 295.36,104.29 PC514.2

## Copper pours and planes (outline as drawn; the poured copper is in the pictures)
GND on TOP (solid shape): 15.11,91.21 15.11,89.99 14.99,89.87 12.98,89.87 12.83,90.02 12.83,91.01 13.18,91.36 14.96,91.36
GND on TOP (solid shape): 28.4,99.19 28.4,91.82 27.76,91.19 23.95,91.19 23.57,91.57 23.57,99.06 24.21,99.69 27.89,99.69
GND on TOP (solid shape): 36.27,88.77 36.27,85.98 35.51,85.22 32.84,85.22 32.46,85.6 32.46,88.65 32.84,89.03 36.02,89.03
GND on TOP (solid shape): 54.05,111.25 54.05,109.09 53.8,108.84 52.27,108.84 52.02,109.09 52.02,111.12 52.27,111.38 53.93,111.38
GND on TOP (solid shape): 60.17,109.86 60.17,108.33 59.92,108.08 57.76,108.08 57.63,108.2 57.63,109.86 58.14,110.36 59.67,110.36
GND on TOP (solid shape): 61.5,103.35 61.5,102.32 61.23,102.06 58.14,102.06 57.76,102.44 57.76,103.35 57.89,103.48 61.37,103.48
GND on TOP (solid shape): 64.65,36.26 64.65,35.4 64.43,35.17 62.39,35.17 62.27,35.3 62.27,36.42 62.34,36.49 64.43,36.49
GND on TOP (solid shape): 293.35,84.33 293.35,82.91 293.14,82.7 291.39,82.7 291.16,82.93 291.16,84.2 291.42,84.45 293.22,84.45
GND on TOP (solid shape): 293.35,43.69 293.35,42.27 293.14,42.06 291.39,42.06 291.16,42.29 291.16,43.56 291.42,43.81 293.22,43.81
GND on TOP (solid shape): 45.51,110.65 45.51,109.25 45.35,109.25 45.19,109.09 43.66,109.09 43.61,109.15 43.61,110.65 43.73,110.78 45.38,110.78
GND on TOP (solid shape): 15.32,103.12 15.32,101.98 15.19,101.85 13.03,101.85 12.78,102.11 12.78,103 13.03,103.25 14.43,103.25 14.43,103.25 15.19,103.25
GND on TOP (solid shape): 68.13,39.36 69.1,39.36 69.71,38.75 69.71,35.3 69.63,35.22 67.93,35.22 67.7,35.45 67.7,39.15 67.93,39.37 68.13,39.37
GND on TOP (solid shape): 15.19,97.54 15.19,96.39 15.06,96.27 13.03,96.27 12.78,96.52 12.78,97.43 12.99,97.64 13.01,97.66 13.04,97.66 15.06,97.66
GND on TOP (solid shape): 48.62,104.63 48.62,103.76 48.23,103.37 46.42,103.37 46.23,103.56 46.23,103.97 46.23,104.86 46.25,104.88 48.36,104.88
GND on TOP (solid shape): 304.75,19.81 304.75,18.95 304.52,18.72 304.52,16.02 304.24,15.75 302.59,15.75 302.34,16 302.34,19.69 302.59,19.94 304.62,19.94
GND on TOP (solid shape): 288.62,30.48 288.75,30.35 288.75,29.46 288.05,28.77 287.03,28.77 286.34,28.07 284.18,28.07 283.9,28.35 283.9,30.3 284.08,30.48 284.48,30.48
GND on TOP (solid shape): 288.88,70.99 288.88,69.95 288.62,69.7 287.73,69.7 287.1,69.06 283.95,69.06 283.8,69.22 283.8,70.87 283.92,70.99 286.97,70.99 287.1,71.12 288.75,71.12
GND on TOP (solid shape): 59.39,59.94 59.39,56.26 59.26,56.13 46.18,56.13 45.77,56.54 45.77,58.14 46.18,58.55 48.46,58.55 48.85,58.93 48.85,59.94 49.23,60.33 59.01,60.33
GND on TOP (solid shape): 296.62,30.48 296.7,30.4 296.7,29.16 296.65,29.11 295.33,29.11 295.1,29.34 295.02,29.34 294.13,29.34 294.13,29.34 292.3,29.34 292.05,29.59 292.05,30.35 292.18,30.48 293.09,30.48
GND on TOP (solid shape): 64.34,48.51 64.34,47.5 64.81,47.03 65.37,47.03 66.37,46.03 66.37,44.76 66.36,44.75 63.96,44.75 62.58,46.12 61.91,46.12 61.31,46.71 61.31,48.54 61.67,48.9 63.96,48.9
GND on TOP (solid shape): 59.02,36.12 59.02,34.6 58.98,34.56 57.26,34.56 57.26,34.56 55.23,34.56 55.13,34.66 55.13,35.45 55.15,35.47 55.41,35.47 55.56,35.47 55.66,35.57 55.68,35.57 55.82,35.71 57.51,35.71 57.72,35.93 57.72,36.13 57.77,36.19 58.96,36.19
GND on TOP (solid shape): 287.17,24.94 287.19,24.91 287.19,24.87 287.18,24.72 287.22,24.57 287.22,24.56 287.22,23.75 286.97,23.5 284.43,23.5 284.3,23.37 284.3,22.61 284.18,22.48 283.67,22.48 283.54,22.61 283.54,24.51 284.05,25.02 287.1,25.02
GND on TOP (solid shape): 282.05,112.9 282.05,111.38 282.86,110.57 290.07,110.57 291,109.64 291,105.32 291.67,104.65 293.7,104.65 293.83,104.52 293.83,103.5 294.78,102.56 294.78,100.26 294.34,99.82 282.65,99.82 281.39,101.09 281.39,107.17 281.12,107.44 280.17,107.44 280.07,107.54 280.07,113.18 280.19,113.31 281.65,113.31
GND on TOP (solid shape): 282.36,7.45 283.26,9.11 285.14,9.25 286.12,8.26 286.18,8.12 286.23,7.97 286.31,7.88 286.31,6.79 285.95,6.43 285.9,6.43 285.79,6.54 285.79,7.45 284.33,8.92 282.87,7.45 282.87,1.5 282.85,1.45 282.79,1.43 282.58,1.43 282.54,1.45 282.51,1.5 282.51,5.95 282.43,5.95 282.38,5.97 282.36,6.02
GND on TOP (solid shape): outline of 172 points within 0.59,108 11,117.73
GND on TOP (solid shape): 320.78,117.74 321.32,117.51 321.54,116.97 321.54,9.68 321.32,9.14 320.78,8.92 297.74,8.92 296.52,8.43 295.96,7.24 295.96,7.21 295.89,7.14 295.61,7.14 295.5,7.19 295.46,7.3 296.18,8.81 297.74,9.42 320.78,9.42 320.96,9.5 321.03,9.68 321.03,116.97 320.96,117.15 320.78,117.23 2,117.23 1.3,116.94 1.02,116.24 1.02,34.44 1.03,34.28 1.05,34.15 1.09,34.03 1.15,33.92 1.24,33.79 1.3,33.71 1.38,33.64 1.51,33.56 1.62,33.5 1.75,33.46 1.87,33.43 2.03,33.42 29.75,33.42 29.91,33.31 30.08,33.2 30.15,33.03 30,32.92 2.02,32.92 1.81,32.93 1.61,32.97 1.43,33.03 1.25,33.12 1.08,33.23 0.95,33.35 0.83,33.49 0.71,33.66 0.62,33.84 0.56,34.02 0.52,34.21 0.51,34.42 0.51,116.24 0.94,117.3 2,117.74
GND on TOP (solid shape): outline of 343 points within 28,32.9 43,42.9
GND on TOP (solid shape): outline of 343 points within 128,32.9 143,42.9
GND on TOP (solid shape): outline of 343 points within 172.05,105 187.05,115
GND on TOP (solid shape): outline of 343 points within 305.25,62.77 320.25,72.77
GND on TOP (solid shape): outline of 343 points within 305.25,102 320.25,112
GND on TOP (solid shape): outline of 343 points within 305.25,11.41 320.25,21.41
GND on TOP (solid shape): outline of 370 points within 140.84,1.43 213.18,33.42
GND on BOTTOM (solid shape): 45.59,110.73 45.59,109.2 45.43,109.04 43.72,109.04 43.61,109.15 43.61,110.7 43.71,110.8 45.51,110.8
GND on BOTTOM (solid shape): 299.04,115.32 299.04,113.28 298.53,112.78 288.88,112.78 288.62,113.03 288.62,114.68 289.51,115.57 298.78,115.57
GND on BOTTOM (solid shape): 46.18,91.82 48.34,91.82 48.97,91.19 48.97,87.25 48.21,86.49 44.4,86.49 44.27,86.61 44.27,92.2 44.53,92.46 45.54,92.46
GND on BOTTOM (solid shape): 275.92,113.79 275.92,98.81 275.54,98.42 274.14,98.42 273.76,98.81 273.76,111 273.13,111.63 273.13,113.67 273.38,113.92 275.79,113.92
GND on BOTTOM (solid shape): 69.66,40.05 69.66,36.39 68.5,35.23 64.28,35.23 64.09,35.43 64.09,36.31 64.21,36.44 65.49,36.44 65.49,36.44 66.87,36.44 67.77,37.34 67.77,39.4 68.48,40.11 69.6,40.11
GND on BOTTOM (solid shape): 282.65,113.16 282.65,108.58 282.14,108.08 281.26,108.08 280.35,108.99 280.35,112.33 279.95,112.73 279.48,112.73 279.41,112.8 279.41,113.34 279.86,113.79 282.02,113.79
GND on BOTTOM (solid shape): 64.64,47.19 65.46,47.19 65.92,46.73 65.92,45.54 64.7,44.31 62.69,44.31 61.71,43.34 61.71,38.98 61.27,38.54 58.7,38.54 58.27,38.96 58.27,47.88 58.78,48.39 63.45,48.39
GND on BOTTOM (solid shape): 303.66,61.27 303.66,56.02 303.39,55.75 298.35,55.75 297.77,56.34 297.77,61.19 298.22,61.65 303.29,61.65
GND on BOTTOM (solid shape): 57.08,60.22 57.08,58.19 57.72,57.54 57.74,57.54 57.74,56.26 57.48,56.01 46.43,56.01 45.8,56.64 45.8,58.17 46.18,58.55 48.85,58.55 49.1,58.8 49.1,60.07 49.35,60.33 56.97,60.33
GND on BOTTOM (solid shape): 60.28,111.38 60.28,108.46 59.51,107.7 56.59,107.7 55.86,106.96 55.86,104.06 54.84,103.04 47.32,103.04 46.9,103.46 46.9,103.85 47.96,104.91 48.26,104.91 48.26,104.91 48.44,104.91 48.45,104.92 48.59,104.92 50.24,106.57 50.24,110.74 51.26,111.76 59.89,111.76
GND on BOTTOM (solid shape): 295.54,104.34 295.54,103.77 295.66,103.64 295.66,102.13 294.39,100.86 293.67,100.86 293.51,100.7 290.99,100.7 290.58,101.1 290.58,101.53 291.03,101.98 291.16,101.98 291.92,102.74 291.92,102.87 293.45,104.39 295.48,104.39
GND on BOTTOM (solid shape): 282.59,8.38 283.75,9.34 285.25,9.19 285.45,9.19 286.25,8.4 286.25,6.77 286.21,6.73 285.88,6.73 285.79,6.82 285.79,7.45 285.74,7.82 285.61,8.15 285.61,8.16 284.26,8.91 282.99,8.03 282.87,7.94 282.74,7.98 282.59,8.13
GND on BOTTOM (solid shape): outline of 108 points within 140.85,9.56 212.51,33.42
GND on BOTTOM (solid shape): outline of 343 points within 28,32.9 43,42.9
GND on BOTTOM (solid shape): outline of 343 points within 128,32.9 143,42.9
GND on BOTTOM (solid shape): outline of 343 points within 172.05,105 187.05,115
GND on BOTTOM (solid shape): outline of 343 points within 305.25,62.77 320.25,72.77
GND on BOTTOM (solid shape): outline of 343 points within 305.25,102 320.25,112
GND on BOTTOM (solid shape): outline of 343 points within 305.25,11.41 320.25,21.41
GND on GND (solid shape): outline of 13704 points within 0.51,5.69 321.54,117.74
GND on IN1 (solid shape): outline of 115 points within 140.85,5.66 213.18,33.42
GND on IN1 (solid shape): 320.78,117.74 321.32,117.51 321.54,116.97 321.54,9.68 321.32,9.14 320.78,8.92 297.74,8.92 296.48,8.39 295.96,7.14 295.96,5.69 295.45,5.69 295.45,7.14 296.12,8.75 297.74,9.42 320.78,9.42 320.96,9.5 321.03,9.68 321.03,116.97 320.96,117.15 320.78,117.23 2,117.23 1.3,116.94 1.02,116.24 1.02,34.44 1.03,34.28 1.05,34.15 1.09,34.03 1.15,33.92 1.24,33.79 1.3,33.71 1.38,33.64 1.51,33.56 1.62,33.5 1.75,33.46 1.87,33.43 2.03,33.42 29.75,33.42 29.91,33.31 30.08,33.2 30.15,33.03 30,32.92 2.02,32.92 1.81,32.93 1.61,32.97 1.43,33.03 1.25,33.12 1.08,33.23 0.95,33.35 0.83,33.49 0.71,33.66 0.62,33.84 0.56,34.02 0.52,34.21 0.51,34.42 0.51,116.24 0.94,117.3 2,117.74
GND on VCC1 (solid shape): outline of 15616 points within 1.02,5.69 321.03,117.23
GND on IN2 (solid shape): outline of 115 points within 140.85,5.69 213.18,33.42
GND on IN2 (solid shape): 320.78,117.74 321.32,117.51 321.54,116.97 321.54,9.68 321.32,9.14 320.78,8.92 297.74,8.92 296.48,8.39 295.96,7.14 295.96,5.69 295.45,5.69 295.45,7.14 296.12,8.75 297.74,9.42 320.78,9.42 320.96,9.5 321.03,9.68 321.03,116.97 320.96,117.15 320.78,117.23 2,117.23 1.3,116.94 1.02,116.24 1.02,34.44 1.03,34.28 1.05,34.15 1.09,34.03 1.15,33.92 1.24,33.79 1.3,33.71 1.38,33.64 1.51,33.56 1.62,33.5 1.75,33.46 1.87,33.43 2.03,33.42 29.75,33.42 29.91,33.31 30.08,33.2 30.15,33.03 30,32.92 2.02,32.92 1.81,32.93 1.61,32.97 1.43,33.03 1.25,33.12 1.08,33.23 0.95,33.35 0.83,33.49 0.71,33.66 0.62,33.84 0.56,34.02 0.52,34.21 0.51,34.42 0.51,116.24 0.94,117.3 2,117.74
GND on GND1 (solid shape): outline of 14187 points within 0.51,5.69 321.54,117.74
GND_L on IN1 (solid shape): outline of 383 points within -19.49,-9.03 -2.51,364.68
P0V9 on TOP (solid shape): 26.62,89.92 26.62,86.11 26.11,85.6 23.19,85.6 22.68,86.11 22.68,89.53 23.32,90.17 26.37,90.17
P0V9 on TOP (solid shape): 52.4,63.75 52.4,62.74 52.53,62.61 54.31,62.61 54.56,62.36 60.53,62.36 61.55,61.34 61.55,49.66 60.91,49.02 54.89,49.02 52.88,47.02 52.88,40.79 50.09,38 46.15,38 43.26,40.89 43.26,49.3 44.53,50.57 44.53,53.34 46.05,54.86 59.51,54.86 59.89,55.24 59.89,60.33 59.51,60.71 49.61,60.71 49.23,61.09 49.23,62.48 50.75,64.01 52.15,64.01
P0V9 on BOTTOM (solid shape): 26.62,89.92 26.62,86.11 26.11,85.6 23.19,85.6 22.68,86.11 22.68,89.53 23.32,90.17 26.37,90.17
P0V9 on BOTTOM (solid shape): 60.53,54.23 60.53,50.8 59.77,50.04 46.18,50.04 45.16,51.05 45.16,52.32 46.94,54.1 46.94,54.99 47.32,55.37 59.39,55.37
P0V9 on BOTTOM (solid shape): outline of 122 points within 49.2,60.76 57.09,63.73
P0V9 on VCC1 (solid shape): outline of 251 points within 21.03,48.9 73.74,90.3
P0V9_A on TOP (solid shape): 37.29,98.81 37.29,96.52 38.94,94.87 43.13,94.87 44.02,93.98 44.02,86.11 43.26,85.34 38.69,85.34 38.05,85.98 38.05,89.15 37.54,89.66 32.34,89.66 31.7,89.03 31.7,85.09 31.57,84.96 28.02,84.96 27.26,85.72 27.26,90.04 29.41,92.2 29.41,99.31 30.3,100.2 35.89,100.2
P0V9_A on BOTTOM (solid shape): 44.02,93.98 44.02,86.11 43.26,85.34 38.69,85.34 38.05,85.98 38.05,89.15 37.54,89.66 32.34,89.66 31.7,89.03 31.7,85.09 31.57,84.96 28.02,84.96 27.26,85.72 27.26,90.04 32.08,94.87 43.13,94.87
P0V9_A on VCC (solid shape): 76.4,91.97 76.4,64.24 61.06,48.9 55.22,48.9 55.07,48.75 54.92,48.9 41.59,48.9 28.98,61.5 47.58,61.5 47.58,61.18 47.8,60.96 48.88,60.96 49.1,61.18 49.1,61.5 48.88,61.72 47.8,61.72 47.58,61.5 28.98,61.5 21.03,69.45 21.03,81.46 23.75,81.46 23.75,84.66 21.03,84.66 21.03,88.54 25.2,92.71 75.66,92.71
P0V9_AGND on TOP (solid shape): 68.74,44.36 68.74,41.67 68.72,41.64 67.19,41.64 67.12,41.72 67.12,44.34 67.17,44.39 68.72,44.39
P0V9_AGND on BOTTOM (solid shape): 69.93,45.34 69.93,44.45 70.31,44.07 71.83,44.07 72.21,43.69 72.21,42.93 71.96,42.67 69.55,42.67 68.91,43.31 68.91,45.21 69.17,45.47 69.8,45.47
P1V8 on TOP (solid shape): 48.97,94.61 48.97,92.33 48.72,92.08 45.92,92.08 45.67,92.33 45.67,94.49 45.92,94.74 48.85,94.74
P1V8 on TOP (solid shape): 57.86,107.57 61.19,107.57 61.32,107.44 61.32,104.52 60.68,103.89 57.76,103.89 57.51,103.63 57.51,102.49 57.38,102.36 54.21,102.36 53.7,102.87 53.7,106.3 55.86,108.46 56.97,108.46
P1V8 on BOTTOM (solid shape): 61.55,106.43 61.55,104.9 61.04,104.39 57.48,104.39 57.1,104.78 57.1,106.55 57.49,106.94 61.03,106.94
P1V8 on IN1 (solid shape): outline of 14902 points within 23.19,33.78 122.99,115.7
P1V8_A on TOP (solid shape): 51.36,93.57 51.36,90.12 51.13,89.89 51.13,88.01 50.5,87.38 49.35,87.38 49.24,87.49 49.24,87.95 49.23,87.95 49.23,90.3 49.35,90.42 49.35,93.6 49.48,93.73 51.21,93.73
P1V8_A on IN2 (solid shape): outline of 10034 points within 43,69.98 67.01,94.23
